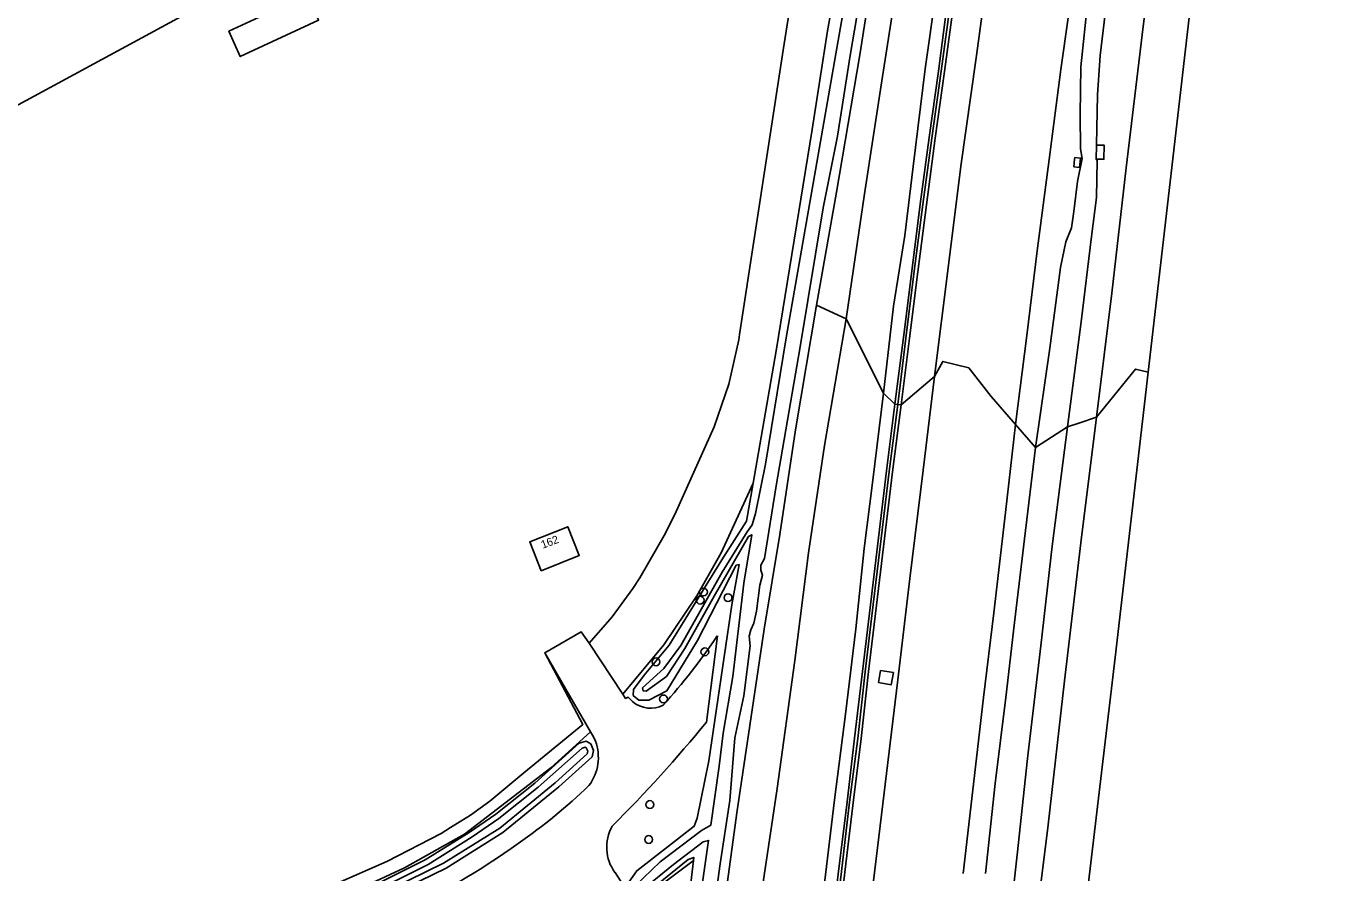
# Model space of a CAD drawing. Extents: x 156061 to 157804, y 383437 to 385640.
# Drawn here: x 157638 to 157801.5, y 383821.9 to 383927.6 of the extents above; entities that cross this region are included whole.
import ezdxf

# ---------------------------------------------------------------- set-up
doc = ezdxf.new("R2010")
doc.units = 0
for name, color, linetype in [('IMGEO_Berm_groen', 7, 'Continuous'), ('IMGEO_Boom', 7, 'Continuous'), ('IMGEO_Bouwland', 7, 'Continuous'), ('IMGEO_Geluidsscherm', 7, 'Continuous'), ('IMGEO_Gemengd_bos', 7, 'Continuous'), ('IMGEO_Grasland_overig', 7, 'Continuous'), ('IMGEO_Groenvoorziening', 7, 'Continuous'), ('IMGEO_Hek', 7, 'Continuous'), ('IMGEO_Muur', 7, 'Continuous'), ('IMGEO_Oever', 7, 'Continuous'), ('IMGEO_Pand', 7, 'Continuous'), ('IMGEO_Pand_nummerreeks', 7, 'Continuous'), ('IMGEO_Rijbaan_autosnelweg', 7, 'Continuous'), ('IMGEO_Rijbaan_autoweg', 7, 'Continuous'), ('IMGEO_Rijbaan_lokaal_gesloten', 7, 'Continuous'), ('IMGEO_Terreindeel_gesloten', 7, 'Continuous'), ('IMGEO_Waterloop', 7, 'Continuous')]:
    doc.layers.add(name, color=color, linetype=linetype)

msp = doc.modelspace()

# ---------------------------------------------------------------- linework, layer by layer
at = {"layer": 'IMGEO_Berm_groen'}
for points in [[(157773.65, 383935.83), (157772.22, 383924), (157771.9, 383919.08), (157771.76, 383912.78), (157772.73, 383912.76), (157772.68, 383911.01), (157771.72, 383911.04), (157771.83, 383910.87), (157771.77, 383906.22), (157771.14, 383901.36), (157769.86, 383890.69), (157768.15, 383877.57), (157769.54, 383878.03), (157771.74, 383878.77), (157773.67, 383894.28), (157775.45, 383909.94), (157777.45, 383926.57), (157779.45, 383942.92)], [(157753.88, 383930.27), (157752.77, 383921.98), (157751.59, 383913.64), (157750.49, 383905.32), (157749.43, 383896.96), (157748.4, 383888.68), (157747.34, 383880.32), (157751.49, 383883.88), (157753.23, 383897.45), (157754.82, 383910.17), (157756.71, 383923.71), (157758.37, 383935.93)], [(157769.08, 383934.9), (157767.31, 383922.22), (157765.83, 383910.99), (157764.36, 383899.56), (157763.05, 383889), (157761.65, 383877.86), (157764.12, 383875.02), (157765.93, 383887.41), (157767.24, 383897.48), (157767.93, 383900.68), (157768.63, 383902.45), (157768.93, 383904.49), (157769.37, 383908.24), (157769.95, 383911.1), (157769.77, 383912.34), (157769.7, 383916.62), (157769.81, 383922.55), (157770.68, 383930.94)], [(157770.68, 383930.94), (157769.81, 383922.55), (157769.7, 383916.62), (157769.77, 383912.34), (157769.95, 383911.1), (157769.37, 383908.24), (157768.93, 383904.49), (157768.63, 383902.45), (157767.93, 383900.68), (157767.24, 383897.48), (157765.93, 383887.41), (157764.12, 383875.02), (157768.15, 383877.57), (157769.86, 383890.69), (157771.14, 383901.36), (157771.77, 383906.22), (157771.83, 383910.87), (157771.72, 383911.04), (157771.76, 383912.78), (157771.9, 383919.08), (157772.22, 383924), (157773.65, 383935.83)], [(157757.88, 383821.78), (157759.11, 383833.03), (157760.42, 383843.77), (157761.51, 383853.15), (157762.75, 383863.57), (157764.12, 383875.02), (157761.65, 383877.86), (157760.37, 383866.89), (157758.93, 383854.34), (157757.65, 383843.75), (157756.29, 383832.23), (157755.1, 383821.77)], [(157763.6, 383810.79), (157765.72, 383827.84), (157767.76, 383845.83), (157769.81, 383863.09), (157771.74, 383878.77), (157769.54, 383878.03), (157768.15, 383877.57), (157766.23, 383862.68), (157764.8, 383850.23), (157763.14, 383836.14), (157761.83, 383824.09), (157760.1, 383808.35)]]:
    msp.add_lwpolyline(points, dxfattribs=at)
for points in [[(157768.91, 383910.06), (157769.02, 383911.02), (157769.05, 383911.25), (157769.77, 383911.17), (157769.64, 383909.98)], [(157737.49, 383804.98), (157736.05, 383805.03), (157735.57, 383804.9), (157736.38, 383810.45), (157737.62, 383819.51), (157739.03, 383830.98), (157740.38, 383841.68), (157741.69, 383852.36), (157742.7, 383862.39), (157743.81, 383870.91), (157745.13, 383881.8), (157740.47, 383891.06), (157737.78, 383875.27), (157735.78, 383861.84), (157734.04, 383848.39), (157731.86, 383832.4), (157729.57, 383817.05), (157728.24, 383805.47), (157730.47, 383805.12), (157731.48, 383804.96), (157735.6, 383804.31), (157736.21, 383804.27), (157736.35, 383804.71), (157737.45, 383804.6)], [(157738.16, 383803.88), (157738.29, 383803.28), (157739.32, 383802.63), (157741.25, 383802.11), (157741.63, 383802.06), (157743.4, 383816.71), (157744.88, 383829.09), (157746.94, 383845.97), (157748.44, 383858.61), (157750.08, 383872.18), (157751.49, 383883.88), (157747.34, 383880.32), (157746.28, 383871.97), (157745.28, 383863.63), (157744.28, 383855.28), (157743.28, 383846.99), (157742.33, 383838.62), (157741.29, 383830.26), (157740.31, 383821.95), (157739.33, 383813.61), (157738.33, 383805.26)], [(157744.78, 383847.14), (157746.37, 383846.87), (157746.11, 383845.36), (157744.52, 383845.64)]]:
    msp.add_lwpolyline(points, close=True, dxfattribs=at)
at = {"layer": 'IMGEO_Boom'}
for centre in [(157722.22, 383855.93), (157722.64, 383856.95), (157725.71, 383856.23), (157722.81, 383849.46), (157716.71, 383848.21), (157717.64, 383843.58), (157715.94, 383830.38), (157715.78, 383826.01)]:
    msp.add_circle(centre, 0.489, dxfattribs=at)
at = {"layer": 'IMGEO_Bouwland'}
for points in [[(157676.59, 383820.43), (157683.07, 383823.26), (157689.84, 383826.75), (157691.04, 383827.5), (157693.54, 383829.05), (157695.92, 383830.81), (157700.2, 383834.34), (157707.55, 383840.38), (157702.8, 383849.36), (157707.35, 383851.98), (157708.34, 383850.55), (157711.22, 383853.86), (157713.8, 383857.36), (157714.67, 383858.73), (157717.72, 383864.02), (157719.04, 383866.63), (157723.96, 383877.57), (157725.79, 383882.93), (157727.04, 383888.46), (157727.15, 383889.11), (157732.6, 383924.65), (157744.46, 384000)], [(157658.89, 383929.67), (157621.02, 383909.21), (157610.74, 383905.07), (157608.98, 383906.43), (157608.72, 383906.11), (157599.51, 383913.73), (157575.52, 383933.59)]]:
    msp.add_lwpolyline(points, dxfattribs=at)
for points in [[(157674.54, 383928.41), (157664.75, 383923.85), (157663.32, 383927.02), (157673.08, 383931.55)], [(157705.68, 383865.1), (157707.12, 383861.49), (157702.37, 383859.6), (157700.93, 383863.21)]]:
    msp.add_lwpolyline(points, close=True, dxfattribs=at)
at = {"layer": 'IMGEO_Geluidsscherm'}
for points in [[(157764.92, 384013.51), (157763.91, 384005.18), (157762.81, 383996.86), (157761.74, 383988.61), (157760.5, 383980.18), (157759.35, 383971.88), (157758.14, 383963.48), (157756.98, 383955.29), (157755.76, 383946.92), (157754.62, 383938.62), (157753.45, 383930.32), (157752.35, 383922.01), (157751.18, 383913.67), (157750.07, 383905.37), (157748.98, 383897.04), (157747.91, 383888.68), (157746.92, 383880.37)], [(157746.92, 383880.37), (157745.86, 383872.01), (157744.83, 383863.64), (157743.85, 383855.37), (157742.84, 383846.98), (157741.93, 383838.63), (157740.86, 383830.33), (157739.87, 383822.02), (157738.87, 383813.69), (157737.88, 383805.34), (157736.87, 383796.97), (157735.93, 383788.66), (157734.89, 383780.25), (157733.9, 383771.97), (157732.87, 383763.57), (157731.84, 383755.22), (157730.89, 383746.94), (157729.87, 383738.63), (157728.87, 383730.26), (157727.86, 383721.89), (157726.92, 383713.54)]]:
    msp.add_lwpolyline(points, dxfattribs=at)
at = {"layer": 'IMGEO_Gemengd_bos'}
msp.add_lwpolyline([(157713.42, 383753.67), (157715.97, 383773.86), (157717.9, 383790.43), (157719.4, 383806.37), (157721.38, 383823.41), (157721.34, 383823.37), (157714.13, 383817.93), (157710.52, 383815.81), (157708.53, 383815.04), (157705.69, 383813.65), (157705.05, 383813.33), (157667.91, 383797.83), (157663.7, 383796.28), (157646.96, 383790.11)], dxfattribs=at)
at = {"layer": 'IMGEO_Grasland_overig'}
for points in [[(157756.49, 384021.7), (157756.53, 384020.83), (157754.52, 384003.56), (157750.88, 383978.38), (157747.85, 383959.57), (157744.91, 383941.57), (157742.19, 383924.08), (157739.28, 383906.91), (157736.76, 383892.78), (157740.47, 383891.06), (157742.76, 383906.7), (157745, 383921.38), (157747.42, 383936.87), (157749.52, 383950.31), (157751.2, 383960.83), (157752.41, 383968.04), (157754.82, 383984.74), (157757.45, 384003.59), (157759.69, 384019.03), (157759.95, 384021.46)], [(157745.13, 383881.8), (157743.81, 383870.91), (157742.7, 383862.39), (157741.69, 383852.36), (157740.38, 383841.68), (157739.03, 383830.98), (157737.62, 383819.51), (157736.38, 383810.45), (157735.57, 383804.9), (157736.05, 383805.03), (157737.49, 383804.98), (157738.55, 383813.66), (157739.53, 383822.04), (157740.54, 383830.35), (157741.53, 383838.68), (157742.51, 383847.02), (157743.5, 383855.36), (157744.51, 383863.72), (157745.52, 383872.08), (157746.57, 383880.42)]]:
    msp.add_lwpolyline(points, close=True, dxfattribs=at)
for points in [[(157747.42, 383936.87), (157745, 383921.38), (157742.76, 383906.7), (157740.47, 383891.06), (157745.13, 383881.8), (157746.39, 383892.64), (157747.79, 383901.51), (157748.84, 383910.1), (157750.34, 383922.31), (157751.68, 383931.73)], [(157751.68, 383931.73), (157750.34, 383922.31), (157748.84, 383910.1), (157747.79, 383901.51), (157746.39, 383892.64), (157745.13, 383881.8), (157746.57, 383880.42), (157747.62, 383888.73), (157748.69, 383897.05), (157749.73, 383905.39), (157750.83, 383913.74), (157751.99, 383922.04), (157753.11, 383930.4)], [(157729.57, 383817.05), (157731.86, 383832.4), (157734.04, 383848.39), (157735.78, 383861.84), (157737.78, 383875.27), (157740.47, 383891.06), (157736.76, 383892.78), (157734.15, 383877.2), (157732.17, 383864.14), (157730.24, 383852.3), (157726.8, 383829.34), (157723.74, 383806.67)], [(157760.1, 383808.35), (157761.83, 383824.09), (157763.14, 383836.14), (157764.8, 383850.23), (157766.23, 383862.68), (157768.15, 383877.57), (157764.12, 383875.02), (157762.75, 383863.57), (157761.51, 383853.15), (157760.42, 383843.77), (157759.11, 383833.03), (157757.88, 383821.78)]]:
    msp.add_lwpolyline(points, dxfattribs=at)
at = {"layer": 'IMGEO_Groenvoorziening'}
for points in [[(157744.46, 384000), (157732.6, 383924.65), (157727.15, 383889.11), (157727.04, 383888.46), (157725.79, 383882.93), (157723.96, 383877.57), (157719.04, 383866.63), (157717.72, 383864.02), (157714.67, 383858.73), (157713.8, 383857.36), (157711.22, 383853.86), (157708.34, 383850.55), (157712.55, 383844.18), (157717.67, 383850.33), (157721.81, 383856.45), (157724.85, 383861.84), (157728.84, 383870.54), (157731.71, 383887.1), (157736.23, 383914.72), (157738.15, 383927.08), (157740.65, 383940.97)], [(157569.52, 383941.83), (157610.5, 383908.34), (157608.98, 383906.43), (157610.74, 383905.07), (157621.02, 383909.21), (157658.89, 383929.67), (157663.41, 383932.41), (157671.29, 383938.14), (157689.24, 383951.93), (157700.65, 383965.44), (157683.71, 383998.2)], [(157723.74, 383806.67), (157726.8, 383829.34), (157730.24, 383852.3), (157732.17, 383864.14), (157734.15, 383877.2), (157736.76, 383892.78), (157739.28, 383906.91), (157742.19, 383924.08), (157744.91, 383941.57)], [(157740.65, 383940.97), (157738.15, 383927.08), (157736.23, 383914.72), (157731.71, 383887.1), (157728.84, 383870.54), (157728.02, 383865.78), (157724.92, 383860.95), (157718.34, 383850.29), (157715.24, 383846.55), (157713.91, 383844.78), (157713.86, 383844.02), (157714.57, 383843.43), (157715.82, 383843.44), (157718.04, 383844.6), (157721.91, 383850.89), (157726.74, 383860.3), (157727.08, 383860.36), (157726.2, 383855.35), (157723.31, 383835.83), (157721.83, 383828.67), (157721.47, 383827.67), (157714.3, 383822.12), (157713.31, 383820.67)], [(157743.43, 383938.4), (157740.96, 383923.97), (157739.37, 383913.92), (157737.58, 383904.96), (157734.74, 383887.57), (157731.71, 383870.23), (157730.25, 383861.12), (157729.81, 383860.31), (157729.8, 383859.66), (157730, 383859.03), (157729.66, 383857.79), (157729.27, 383854.55), (157728.93, 383853.04), (157728.57, 383852.22), (157728.34, 383851.42), (157728.46, 383850.2), (157727.7, 383843.96), (157726.56, 383838.73), (157725.94, 383830.88), (157724.73, 383822.98), (157722.58, 383807.48)], [(157714.11, 383820.21), (157717.23, 383823.22), (157722.38, 383827.14), (157723.55, 383827.8), (157724.61, 383835.18), (157725.08, 383839.29), (157726.29, 383846.4), (157727.68, 383858.04), (157728.68, 383864.09), (157728.28, 383863.86), (157723.97, 383856.41), (157720.31, 383849.89), (157718.01, 383846.39), (157715.46, 383844.56), (157715.08, 383844.61), (157715.03, 383844.95), (157717.69, 383847.37), (157719.81, 383850.27), (157724.99, 383859.44), (157728.1, 383864.48), (157728.74, 383865.32), (157729.12, 383866.76), (157730.37, 383872.9), (157732.96, 383888.69), (157740.91, 383934.24)], [(157709.13, 383838.3), (157708.9, 383838.83), (157708.52, 383839.48), (157702.8, 383849.36), (157707.55, 383840.38), (157700.2, 383834.34), (157695.92, 383830.81), (157693.54, 383829.05), (157691.04, 383827.5), (157689.84, 383826.75), (157683.07, 383823.26), (157676.59, 383820.43), (157634.61, 383803.39), (157626.26, 383803.73), (157620.27, 383810.26), (157611.86, 383828.59), (157592.66, 383877.06), (157588.09, 383888.13), (157579.36, 383907.86), (157571.61, 383923.12), (157569.27, 383927.73)], [(157713.31, 383820.67), (157714.3, 383822.12), (157721.47, 383827.67), (157721.83, 383828.67), (157723.31, 383835.83), (157726.2, 383855.35), (157727.08, 383860.36), (157726.74, 383860.3), (157721.91, 383850.89), (157718.04, 383844.6), (157715.82, 383843.44), (157714.57, 383843.43), (157713.86, 383844.02), (157713.91, 383844.78), (157715.24, 383846.55), (157718.34, 383850.29), (157724.92, 383860.95), (157728.02, 383865.78), (157728.84, 383870.54), (157724.85, 383861.84), (157721.81, 383856.45), (157717.67, 383850.33), (157712.55, 383844.18), (157712.91, 383843.64), (157713.21, 383843.82), (157713.77, 383843.25)], [(157724.37, 383851.46), (157723.02, 383840.68)], [(157670.26, 383815.6), (157675.68, 383817.98), (157682.12, 383820.61), (157687.87, 383823.49), (157693.34, 383826.91), (157696.67, 383829.17), (157701.54, 383833.07), (157707.12, 383838.06), (157707.97, 383838.29), (157708.54, 383837.95), (157708.89, 383837.12), (157708.71, 383836.34), (157704.54, 383832.59), (157697.57, 383826.89), (157690.49, 383822.43), (157683.9, 383819.21), (157663.05, 383810.49), (157638.43, 383800.07)], [(157721.2, 383811.27), (157723.28, 383825.9), (157722.58, 383825.74), (157718.88, 383822.88), (157715.1, 383819.81)], [(157711.58, 383821.89), (157714.13, 383817.93), (157721.34, 383823.37), (157721.38, 383823.41), (157721.42, 383823.77), (157720.72, 383823.51), (157715.23, 383819.06)], [(157715.23, 383819.06), (157720.72, 383823.51), (157721.42, 383823.77), (157721.38, 383823.41), (157719.4, 383806.37)]]:
    msp.add_lwpolyline(points, dxfattribs=at)
for centre, radius, start, end in [((157656.96, 383897.04), 81.37, 318.1862, 325.9359), ((157716.04, 383845.88), 3.47, 229.2379, 296.9022), ((157586.52, 383952.67), 176.56, 314.9358, 320.6362), ((157703.69, 383836.27), 5.81, 322.9144, 20.5475), ((157658.47, 383884.6), 71.92, 304.7814, 313.8821), ((157715.91, 383825.06), 5.37, 150.8509, 216.1896), ((157639.49, 383909.94), 103.57, 295.653, 305.4074)]:
    msp.add_arc(centre, radius, start, end, dxfattribs=at)
at = {"layer": 'IMGEO_Hek'}
for points in [[(157608.98, 383906.43), (157610.74, 383905.07), (157621.02, 383909.21), (157658.89, 383929.67), (157663.41, 383932.41), (157671.29, 383938.14), (157689.24, 383951.93), (157700.65, 383965.44)], [(157708.52, 383839.48), (157703.56, 383834.99), (157692.77, 383826.67), (157685.27, 383822.48), (157681.68, 383820.81), (157676.7, 383819.01)]]:
    msp.add_lwpolyline(points, dxfattribs=at)
at = {"layer": 'IMGEO_Muur'}
for points in [[(157753.11, 383930.4), (157751.99, 383922.04), (157750.83, 383913.74), (157749.73, 383905.39), (157748.69, 383897.05), (157747.62, 383888.73), (157746.57, 383880.42), (157747.34, 383880.32), (157748.4, 383888.68), (157749.43, 383896.96), (157750.49, 383905.32), (157751.59, 383913.64), (157752.77, 383921.98), (157753.88, 383930.27)], [(157739.33, 383813.61), (157740.31, 383821.95), (157741.29, 383830.26), (157742.33, 383838.62), (157743.28, 383846.99), (157744.28, 383855.28), (157745.28, 383863.63), (157746.28, 383871.97), (157747.34, 383880.32), (157746.57, 383880.42), (157745.52, 383872.08), (157744.51, 383863.72), (157743.5, 383855.36), (157742.51, 383847.02), (157741.53, 383838.68), (157740.54, 383830.35), (157739.53, 383822.04), (157738.55, 383813.66)]]:
    msp.add_lwpolyline(points, dxfattribs=at)
at = {"layer": 'IMGEO_Oever'}
for points in [[(157683.9, 383819.21), (157690.49, 383822.43), (157697.57, 383826.89), (157704.54, 383832.59), (157708.71, 383836.34), (157708.89, 383837.12), (157708.54, 383837.95), (157707.97, 383838.29), (157707.12, 383838.06), (157701.54, 383833.07), (157696.67, 383829.17), (157693.34, 383826.91), (157687.87, 383823.49), (157682.12, 383820.61), (157675.68, 383817.98), (157670.26, 383815.6), (157639.77, 383803.64)], [(157640.04, 383803.01), (157670.52, 383814.96), (157675.95, 383817.35), (157682.4, 383819.98), (157688.21, 383822.89), (157693.71, 383826.34), (157697.08, 383828.62), (157701.98, 383832.54), (157707.46, 383837.44), (157707.87, 383837.55), (157707.99, 383837.47), (157708.17, 383837.06), (157708.09, 383836.71), (157704.09, 383833.11), (157697.17, 383827.45), (157690.15, 383823.04), (157683.62, 383819.84), (157662.79, 383811.12), (157638.17, 383800.71)]]:
    msp.add_lwpolyline(points, dxfattribs=at)
at = {"layer": 'IMGEO_Pand'}
for points in [[(157664.75, 383923.85), (157674.54, 383928.41), (157673.08, 383931.55), (157663.32, 383927.02)], [(157702.37, 383859.6), (157707.12, 383861.49), (157705.68, 383865.1), (157700.93, 383863.21)]]:
    msp.add_lwpolyline(points, close=True, dxfattribs=at)
at = {"layer": 'IMGEO_Rijbaan_autosnelweg'}
for points in [[(157779.45, 383942.92), (157777.45, 383926.57), (157775.45, 383909.94), (157773.67, 383894.28), (157771.74, 383878.77), (157776.63, 383884.79), (157778.21, 383884.4), (157801.54, 384086.27)], [(157751.53, 383658.26), (157774.09, 383848.76), (157778.21, 383884.4), (157776.63, 383884.79), (157771.74, 383878.77), (157769.81, 383863.09), (157767.76, 383845.83), (157765.72, 383827.84), (157763.6, 383810.79)]]:
    msp.add_lwpolyline(points, dxfattribs=at)
at = {"layer": 'IMGEO_Rijbaan_autoweg'}
for points in [[(157758.37, 383935.93), (157756.71, 383923.71), (157754.82, 383910.17), (157753.23, 383897.45), (157751.49, 383883.88), (157752.56, 383885.76), (157755.78, 383884.94), (157758.59, 383881.39), (157761.65, 383877.86), (157763.05, 383889), (157764.36, 383899.56), (157765.83, 383910.99), (157767.31, 383922.22), (157769.08, 383934.9)], [(157755.1, 383821.77), (157756.29, 383832.23), (157757.65, 383843.75), (157758.93, 383854.34), (157760.37, 383866.89), (157761.65, 383877.86), (157758.59, 383881.39), (157755.78, 383884.94), (157752.56, 383885.76), (157751.49, 383883.88), (157750.08, 383872.18), (157748.44, 383858.61), (157746.94, 383845.97), (157744.88, 383829.09), (157743.4, 383816.71)]]:
    msp.add_lwpolyline(points, dxfattribs=at)
at = {"layer": 'IMGEO_Rijbaan_lokaal_gesloten'}
for points in [[(157713.77, 383843.25), (157713.21, 383843.82), (157712.91, 383843.64), (157712.55, 383844.18), (157708.34, 383850.55), (157707.35, 383851.98), (157702.8, 383849.36), (157708.52, 383839.48), (157708.9, 383838.83), (157709.13, 383838.3)], [(157723.02, 383840.68), (157724.37, 383851.46)], [(157707.84, 383817.88), (157708.38, 383817.46), (157708.74, 383816.97), (157708.85, 383816.19), (157708.53, 383815.04), (157710.52, 383815.81), (157714.13, 383817.93), (157711.58, 383821.89)]]:
    msp.add_lwpolyline(points, dxfattribs=at)
for centre, radius, start, end in [((157656.96, 383897.04), 81.37, 318.1862, 325.9359), ((157716.04, 383845.88), 3.47, 229.2379, 296.9022), ((157586.52, 383952.67), 176.56, 314.9358, 320.6362), ((157703.69, 383836.27), 5.81, 322.9144, 20.5475), ((157658.47, 383884.6), 71.92, 304.7814, 313.8821), ((157715.91, 383825.06), 5.37, 150.8509, 216.1896), ((157639.49, 383909.94), 103.57, 295.653, 305.4074)]:
    msp.add_arc(centre, radius, start, end, dxfattribs=at)
at = {"layer": 'IMGEO_Terreindeel_gesloten'}
for points in [[(157771.72, 383911.04), (157772.68, 383911.01), (157772.73, 383912.76), (157771.76, 383912.78)], [(157768.91, 383910.06), (157769.64, 383909.98), (157769.77, 383911.17), (157769.05, 383911.25), (157769.02, 383911.02)], [(157744.78, 383847.14), (157744.52, 383845.64), (157746.11, 383845.36), (157746.37, 383846.87)]]:
    msp.add_lwpolyline(points, close=True, dxfattribs=at)
at = {"layer": 'IMGEO_Waterloop'}
for points in [[(157722.58, 383807.48), (157724.73, 383822.98), (157725.94, 383830.88), (157726.56, 383838.73), (157727.7, 383843.96), (157728.46, 383850.2), (157728.34, 383851.42), (157728.57, 383852.22), (157728.93, 383853.04), (157729.27, 383854.55), (157729.66, 383857.79), (157730, 383859.03), (157729.8, 383859.66), (157729.81, 383860.31), (157730.25, 383861.12), (157731.71, 383870.23), (157734.74, 383887.57), (157737.58, 383904.96), (157739.37, 383913.92), (157740.96, 383923.97), (157743.43, 383938.4)], [(157740.91, 383934.24), (157732.96, 383888.69), (157730.37, 383872.9), (157729.12, 383866.76), (157728.74, 383865.32), (157728.1, 383864.48), (157724.99, 383859.44), (157719.81, 383850.27), (157717.69, 383847.37), (157715.03, 383844.95), (157715.08, 383844.61), (157715.46, 383844.56), (157718.01, 383846.39), (157720.31, 383849.89), (157723.97, 383856.41), (157728.28, 383863.86), (157728.68, 383864.09), (157727.68, 383858.04), (157726.29, 383846.4), (157725.08, 383839.29), (157724.61, 383835.18), (157723.55, 383827.8), (157722.38, 383827.14), (157717.23, 383823.22), (157714.11, 383820.21)], [(157638.17, 383800.71), (157662.79, 383811.12), (157683.62, 383819.84), (157690.15, 383823.04), (157697.17, 383827.45), (157704.09, 383833.11), (157708.09, 383836.71), (157708.17, 383837.06), (157707.99, 383837.47), (157707.87, 383837.55), (157707.46, 383837.44), (157701.98, 383832.54), (157697.08, 383828.62), (157693.71, 383826.34), (157688.21, 383822.89), (157682.4, 383819.98), (157675.95, 383817.35), (157670.52, 383814.96), (157640.04, 383803.01)], [(157715.1, 383819.81), (157718.88, 383822.88), (157722.58, 383825.74), (157723.28, 383825.9), (157721.2, 383811.27)]]:
    msp.add_lwpolyline(points, dxfattribs=at)

# ---------------------------------------------------------------- texts
at = {"layer": 'IMGEO_Pand_nummerreeks'}
msp.add_text('162', height=1, rotation=20.5292, dxfattribs=at).set_placement((157702.55, 383862.34))

doc.saveas('drawing.dxf')
